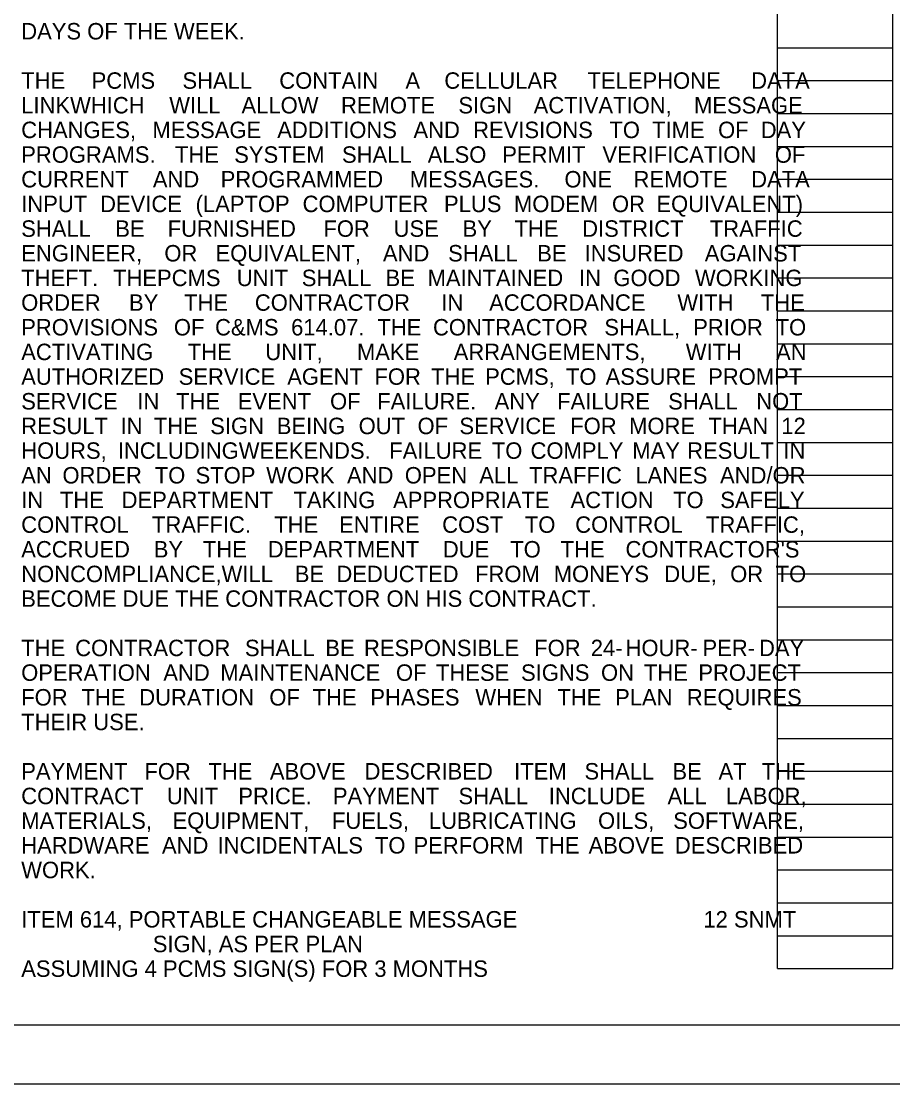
# Model space of a CAD drawing. Extents: x 0 to 34, y 0 to 22.
# Drawn here: x 17.24 to 24.66, y 0 to 9.04 of the extents above; entities that cross this region are included whole.
import ezdxf

# ---------------------------------------------------------------- set-up
doc = ezdxf.new("R2010")
doc.units = 0
for name, color, linetype in [('SH_Border', 7, 'Continuous'), ('SH_Cut_Line', 7, 'Continuous'), ('SH_Data', 7, 'Continuous'), ('SH_Text', 7, 'Continuous')]:
    doc.layers.add(name, color=color, linetype=linetype)

msp = doc.modelspace()

# ---------------------------------------------------------------- linework, layer by layer
at = {"layer": 'SH_Border'}
msp.add_lwpolyline([(1.5, 21.5), (33.5, 21.5), (33.5, 0.5), (1.5, 0.5)], close=True, dxfattribs=at)
at = {"layer": 'SH_Cut_Line'}
msp.add_lwpolyline([(0, 0), (34, 0), (34, 22), (0, 22)], close=True, dxfattribs=at)
at = {"layer": 'SH_Data'}
for p, q in [((23.68, 0.98), (23.68, 21.14)), ((24.66, 0.98), (24.66, 21.14)), ((23.68, 8.82), (24.66, 8.82)), ((23.68, 8.54), (24.66, 8.54)), ((23.68, 8.26), (24.66, 8.26)), ((23.68, 7.98), (24.66, 7.98)), ((23.68, 7.7), (24.66, 7.7)), ((23.68, 7.42), (24.66, 7.42)), ((23.68, 7.14), (24.66, 7.14)), ((23.68, 6.86), (24.66, 6.86)), ((23.68, 6.58), (24.66, 6.58)), ((23.68, 6.3), (24.66, 6.3)), ((23.68, 6.02), (24.66, 6.02)), ((23.68, 5.74), (24.66, 5.74)), ((23.68, 5.46), (24.66, 5.46)), ((23.68, 5.18), (24.66, 5.18)), ((23.68, 4.9), (24.66, 4.9)), ((23.68, 4.62), (24.66, 4.62)), ((23.68, 4.34), (24.66, 4.34)), ((23.68, 4.06), (24.66, 4.06)), ((23.68, 3.78), (24.66, 3.78)), ((23.68, 3.5), (24.66, 3.5)), ((23.68, 3.22), (24.66, 3.22)), ((23.68, 2.94), (24.66, 2.94)), ((23.68, 2.66), (24.66, 2.66)), ((23.68, 2.38), (24.66, 2.38)), ((23.68, 2.1), (24.66, 2.1)), ((23.68, 1.82), (24.66, 1.82)), ((23.68, 1.54), (24.66, 1.54)), ((23.68, 1.26), (24.66, 1.26)), ((23.68, 0.98), (24.66, 0.98))]:
    msp.add_line(p, q, dxfattribs=at)

# ---------------------------------------------------------------- texts
at = {"layer": 'SH_Text'}
for s, p in [('DAYS OF THE WEEK.', (17.24, 8.89)), ('THE ', (17.24, 8.47)), ('PCMS ', (17.8394, 8.47)), ('SHALL ', (18.6127, 8.47)), ('CONTAIN ', (19.437, 8.47)), ('A ', (20.5109, 8.47)), ('CELLULAR ', (20.8423, 8.47)), ('TELEPHONE ', (22.0614, 8.47)), ('DATA ', (23.4545, 8.47)), ('LINKWHICH ', (17.24, 8.26)), ('WILL ', (18.5001, 8.26)), ('ALLOW ', (19.1154, 8.26)), ('REMOTE ', (19.9627, 8.26)), ('SIGN ', (20.9621, 8.26)), ('ACTIVATION, ', (21.6028, 8.26)), ('MESSAGE ', (22.9682, 8.26)), ('CHANGES, ', (17.24, 8.05)), ('MESSAGE ', (18.3568, 8.05)), ('ADDITIONS ', (19.4194, 8.05)), ('AND ', (20.5795, 8.05)), ('REVISIONS ', (21.0875, 8.05)), ('TO ', (22.2478, 8.05)), ('TIME ', (22.6109, 8.05)), ('OF ', (23.1731, 8.05)), ('DAY ', (23.5362, 8.05)), ('PROGRAMS. ', (17.24, 7.84)), ('THE ', (18.5489, 7.84)), ('SYSTEM ', (19.0534, 7.84)), ('SHALL ', (19.9711, 7.84)), ('ALSO ', (20.7006, 7.84)), ('PERMIT ', (21.3357, 7.84)), ('VERIFICATION ', (22.188, 7.84)), ('OF ', (23.6562, 7.84)), ('CURRENT ', (17.24, 7.63)), ('AND ', (18.3608, 7.63)), ('PROGRAMMED ', (18.9382, 7.63)), ('MESSAGES. ', (20.5481, 7.63)), ('ONE ', (21.8649, 7.63)), ('REMOTE ', (22.4532, 7.63)), ('DATA ', (23.4545, 7.63)), ('INPUT ', (17.24, 7.42)), ('DEVICE ', (17.9115, 7.42)), ('(LAPTOP ', (18.7246, 7.42)), ('COMPUTER ', (19.6355, 7.42)), ('PLUS ', (20.8396, 7.42)), ('MODEM ', (21.4353, 7.42)), ('OR ', (22.2698, 7.42)), ('EQUIVALENT) ', (22.6479, 7.42)), ('SHALL ', (17.24, 7.21)), ('BE ', (18.041, 7.21)), ('FURNISHED ', (18.4868, 7.21)), ('FOR ', (19.8128, 7.21)), ('USE ', (20.4105, 7.21)), ('BY ', (20.9975, 7.21)), ('THE ', (21.4398, 7.21)), ('DISTRICT ', (22.0158, 7.21)), ('TRAFFIC ', (23.1026, 7.21)), ('ENGINEER, ', (17.24, 7)), ('OR ', (18.4585, 7)), ('EQUIVALENT, ', (18.8942, 7)), ('AND ', (20.3194, 7)), ('SHALL ', (20.8747, 7)), ('BE ', (21.6333, 7)), ('INSURED ', (22.0366, 7)), ('AGAINST ', (23.0594, 7)), ('THEFT. ', (17.24, 6.79)), ('THEPCMS ', (18.0217, 6.79)), ('UNIT ', (19.0752, 6.79)), ('SHALL ', (19.6286, 6.79)), ('BE ', (20.3419, 6.79)), ('MAINTAINED ', (20.6999, 6.79)), ('IN ', (21.9888, 6.79)), ('GOOD ', (22.2814, 6.79)), ('WORKING ', (22.9762, 6.79)), ('ORDER ', (17.24, 6.58)), ('BY ', (18.1577, 6.58)), ('THE ', (18.6265, 6.58)), ('CONTRACTOR ', (19.229, 6.58)), ('IN ', (20.8169, 6.58)), ('ACCORDANCE ', (21.2238, 6.58)), ('WITH ', (22.8264, 6.58)), ('THE ', (23.5373, 6.58)), ('PROVISIONS ', (17.24, 6.37)), ('OF ', (18.5398, 6.37)), ('C&MS ', (18.8902, 6.37)), ('614.07. ', (19.5378, 6.37)), ('THE ', (20.2723, 6.37)), ('CONTRACTOR ', (20.7459, 6.37)), ('SHALL, ', (22.2049, 6.37)), ('PRIOR ', (22.9613, 6.37)), ('TO ', (23.6631, 6.37)), ('ACTIVATING ', (17.24, 6.16)), ('THE ', (18.6578, 6.16)), ('UNIT, ', (19.3184, 6.16)), ('MAKE ', (20.0984, 6.16)), ('ARRANGEMENTS, ', (20.9221, 6.16)), ('WITH ', (22.8979, 6.16)), ('AN ', (23.6668, 6.16)), ('AUTHORIZED ', (17.24, 5.95)), ('SERVICE ', (18.5805, 5.95)), ('AGENT ', (19.5047, 5.95)), ('FOR ', (20.2476, 5.95)), ('THE ', (20.7294, 5.95)), ('PCMS, ', (21.1896, 5.95)), ('TO ', (21.878, 5.95)), ('ASSURE ', (22.215, 5.95)), ('PROMPT ', (23.0885, 5.95)), ('SERVICE ', (17.24, 5.74)), ('IN ', (18.229, 5.74)), ('THE ', (18.5582, 5.74)), ('EVENT ', (19.0831, 5.74)), ('OF ', (19.8691, 5.74)), ('FAILURE. ', (20.2709, 5.74)), ('ANY ', (21.2704, 5.74)), ('FAILURE ', (21.8028, 5.74)), ('SHALL ', (22.7481, 5.74)), ('NOT ', (23.4979, 5.74)), ('RESULT ', (17.24, 5.53)), ('IN ', (18.0856, 5.53)), ('THE ', (18.3695, 5.53)), ('SIGN ', (18.8491, 5.53)), ('BEING ', (19.4157, 5.53)), ('OUT ', (20.1128, 5.53)), ('OF ', (20.614, 5.53)), ('SERVICE ', (20.9705, 5.53)), ('FOR ', (21.9142, 5.53)), ('MORE ', (22.4155, 5.53)), ('THAN ', (23.0907, 5.53)), ('12 ', (23.7116, 5.53)), ('HOURS, ', (17.24, 5.32)), ('INCLUDINGWEEKENDS. ', (18.0623, 5.32)), ('FAILURE ', (20.3736, 5.32)), ('TO ', (21.2467, 5.32)), ('COMPLY ', (21.5763, 5.32)), ('MAY ', (22.4424, 5.32)), ('RESULT ', (22.9098, 5.32)), ('IN ', (23.7285, 5.32)), ('AN ', (17.24, 5.11)), ('ORDER ', (17.5911, 5.11)), ('TO ', (18.377, 5.11)), ('STOP ', (18.7244, 5.11)), ('WORK ', (19.3257, 5.11)), ('AND ', (20.0136, 5.11)), ('OPEN ', (20.506, 5.11)), ('ALL ', (21.1398, 5.11)), ('TRAFFIC ', (21.5635, 5.11)), ('LANES ', (22.4688, 5.11)), ('AND/OR ', (23.1896, 5.11)), ('IN ', (17.24, 4.9)), ('THE ', (17.5694, 4.9)), ('DEPARTMENT ', (18.0946, 4.9)), ('TAKING ', (19.5582, 4.9)), ('APPROPRIATE ', (20.4058, 4.9)), ('ACTION ', (21.9168, 4.9)), ('TO ', (22.7897, 4.9)), ('SAFELY ', (23.1917, 4.9)), ('CONTROL ', (17.24, 4.69)), ('TRAFFIC. ', (18.3534, 4.69)), ('THE ', (19.3942, 4.69)), ('ENTIRE ', (19.9461, 4.69)), ('COST ', (20.824, 4.69)), ('TO ', (21.528, 4.69)), ('CONTROL ', (21.9567, 4.69)), ('TRAFFIC, ', (23.0701, 4.69)), ('ACCRUED ', (17.24, 4.48)), ('BY ', (18.3683, 4.48)), ('THE ', (18.7867, 4.48)), ('DEPARTMENT ', (19.3389, 4.48)), ('DUE ', (20.8296, 4.48)), ('TO ', (21.4035, 4.48)), ('THE ', (21.8326, 4.48)), ("CONTRACTOR'S ", (22.3848, 4.48)), ('NONCOMPLIANCE,WILL ', (17.24, 4.27)), ('BE ', (19.569, 4.27)), ('DEDUCTED ', (19.9236, 4.27)), ('FROM ', (21.1041, 4.27)), ('MONEYS ', (21.7736, 4.27)), ('DUE, ', (22.7151, 4.27)), ('OR ', (23.2761, 4.27)), ('TO ', (23.6631, 4.27)), ('BECOME DUE THE CONTRACTOR ON HIS CONTRACT.', (17.24, 4.06)), ('THE ', (17.24, 3.64)), ('CONTRACTOR ', (17.6996, 3.64)), ('SHALL ', (19.1446, 3.64)), ('BE ', (19.8291, 3.64)), ('RESPONSIBLE ', (20.1584, 3.64)), ('FOR ', (21.6075, 3.64)), ('24-', (22.0888, 3.64)), ('HOUR-', (22.3853, 3.64)), ('PER-', (23.0404, 3.64)), ('DAY ', (23.5217, 3.64)), ('OPERATION ', (17.24, 3.43)), ('AND ', (18.4498, 3.43)), ('MAINTENANCE ', (18.9349, 3.43)), ('OF ', (20.4308, 3.43)), ('THESE ', (20.771, 3.43)), ('SIGNS ', (21.4954, 3.43)), ('ON ', (22.1762, 3.43)), ('THE ', (22.5417, 3.43)), ('PROJECT ', (23.005, 3.43)), ('FOR ', (17.24, 3.22)), ('THE ', (17.7533, 3.22)), ('DURATION ', (18.2449, 3.22)), ('OF ', (19.3523, 3.22)), ('THE ', (19.7208, 3.22)), ('PHASES ', (20.2124, 3.22)), ('WHEN ', (21.1066, 3.22)), ('THE ', (21.8045, 3.22)), ('PLAN ', (22.2962, 3.22)), ('REQUIRES ', (22.9075, 3.22)), ('THEIR USE.', (17.24, 3.01)), ('PAYMENT ', (17.24, 2.59)), ('FOR ', (18.2887, 2.59)), ('THE ', (18.8337, 2.59)), ('ABOVE ', (19.357, 2.59)), ('DESCRIBED ', (20.1631, 2.59)), ('ITEM ', (21.4366, 2.59)), ('SHALL ', (22.0358, 2.59)), ('BE ', (22.7841, 2.59)), ('AT ', (23.1771, 2.59)), ('THE ', (23.5446, 2.59)), ('CONTRACT ', (17.24, 2.38)), ('UNIT ', (18.4795, 2.38)), ('PRICE. ', (19.0885, 2.38)), ('PAYMENT ', (19.8934, 2.38)), ('SHALL ', (20.9628, 2.38)), ('INCLUDE ', (21.7317, 2.38)), ('ALL ', (22.743, 2.38)), ('LABOR, ', (23.2401, 2.38)), ('MATERIALS, ', (17.24, 2.17)), ('EQUIPMENT, ', (18.5285, 2.17)), ('FUELS, ', (19.8857, 2.17)), ('LUBRICATING ', (20.7105, 2.17)), ('OILS, ', (22.151, 2.17)), ('SOFTWARE, ', (22.791, 2.17)), ('HARDWARE ', (17.24, 1.96)), ('AND ', (18.4382, 1.96)), ('INCIDENTALS ', (18.9118, 1.96)), ('TO ', (20.2514, 1.96)), ('PERFORM ', (20.58, 1.96)), ('THE ', (21.6188, 1.96)), ('ABOVE ', (22.0706, 1.96)), ('DESCRIBED ', (22.8053, 1.96)), ('WORK.', (17.24, 1.75)), ('ITEM 614, PORTABLE CHANGEABLE MESSAGE ', (17.24, 1.33)), ('    12 SNMT', (22.84, 1.33)), ('SIGN, AS PER PLAN', (18.36, 1.12)), ('ASSUMING 4 PCMS SIGN(S) FOR 3 MONTHS', (17.24, 0.91))]:
    msp.add_text(s, height=0.14, dxfattribs=at).set_placement(p)

doc.saveas('drawing.dxf')
